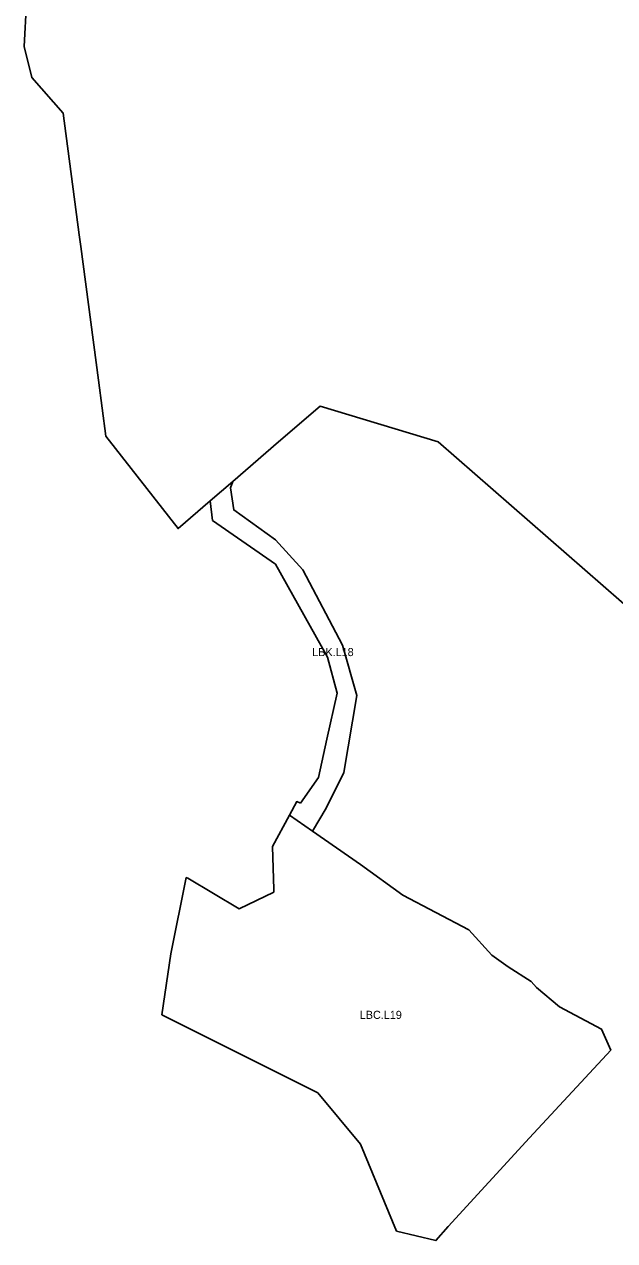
# Model space of a CAD drawing. Extents: x -450188 to -432919, y -1130252 to -1121189.
# Drawn here: x -436560 to -435829, y -1128574 to -1127067 of the extents above; entities that cross this region are included whole.
import ezdxf

# ---------------------------------------------------------------- set-up
doc = ezdxf.new("R2010")
doc.units = 0
for name, color, linetype in [('Vrstva 30', 7, 'Continuous'), ('Vrstva 32', 7, 'Continuous'), ('Vrstva 33', 7, 'Continuous'), ('Vrstva 36', 7, 'Continuous')]:
    doc.layers.add(name, color=color, linetype=linetype)

msp = doc.modelspace()

# ---------------------------------------------------------------- linework, layer by layer
at = {"layer": 'Vrstva 30'}
msp.add_lwpolyline([(-435797.7, -1127801.8), (-436047.1, -1127584.1), (-436193.5, -1127539.8), (-436244.8, -1127584), (-436301.6, -1127633), (-436329.7, -1127657.1), (-436369.4, -1127691.4), (-436458.8, -1127576.8), (-436467.8, -1127507.6), (-436489.7, -1127342), (-436491.6, -1127327.6), (-436511.6, -1127176.5), (-436550.5, -1127132.4), (-436559.7, -1127094.2), (-436557.2, -1127039.4), (-436553.8, -1126965.3), (-436550.6, -1126894.6)], dxfattribs=at)
at = {"layer": 'Vrstva 32'}
for p, q in [((-436231.5, -1128046.6), (-436202.8, -1128066.5)), ((-436202.8, -1128066.5), (-436143.6, -1128107.6))]:
    msp.add_line(p, q, dxfattribs=at)
msp.add_lwpolyline([(-436143.6, -1128107.6), (-436090.9, -1128145.6), (-436009.4, -1128188.4), (-435980.9, -1128219.9), (-435960.4, -1128234.4), (-435932.3, -1128252.4), (-435925.4, -1128260.1), (-435897.2, -1128284), (-435845, -1128311.6), (-435833.5, -1128337.7), (-435934.2, -1128446.2), (-436034.9, -1128556.2), (-436050, -1128573.7), (-436098.7, -1128561.9), (-436143.6, -1128454.2), (-436196.1, -1128390.6), (-436389.3, -1128293.7), (-436378.3, -1128218.2), (-436359.2, -1128123.9), (-436357.1, -1128124.7), (-436293.5, -1128162.4), (-436250.8, -1128141.7), (-436250.9, -1128138.5), (-436252.5, -1128085.2), (-436231.5, -1128046.6)], dxfattribs=at)
at = {"layer": 'Vrstva 33'}
msp.add_line((-436329.7, -1127657.1), (-436301.6, -1127633), dxfattribs=at)
for points in [[(-436301.6, -1127633), (-436304.6, -1127640.7), (-436300.4, -1127668.3), (-436248.7, -1127705.2), (-436214.8, -1127742.5), (-436165.7, -1127835.8), (-436147.9, -1127898.1), (-436164, -1127993.8), (-436186, -1128037.9), (-436202.8, -1128066.5)], [(-436217.8, -1128031.8), (-436195.5, -1128000), (-436185, -1127952.2), (-436172.4, -1127895.2), (-436184.3, -1127850.8), (-436248.7, -1127735.4), (-436326.7, -1127681.2), (-436329.7, -1127657.1)], [(-436202.8, -1128066.5), (-436231.5, -1128046.6), (-436222.3, -1128029.7), (-436217.8, -1128031.8)]]:
    msp.add_lwpolyline(points, dxfattribs=at)

# ---------------------------------------------------------------- texts
at = {"layer": 'Vrstva 36'}
for s, p in [('LBK.L18', (-436203.2, -1127849.4)), ('LBC.L19', (-436144.3, -1128298.9))]:
    msp.add_text(s, height=10, dxfattribs=at).set_placement(p)

doc.saveas('drawing.dxf')
